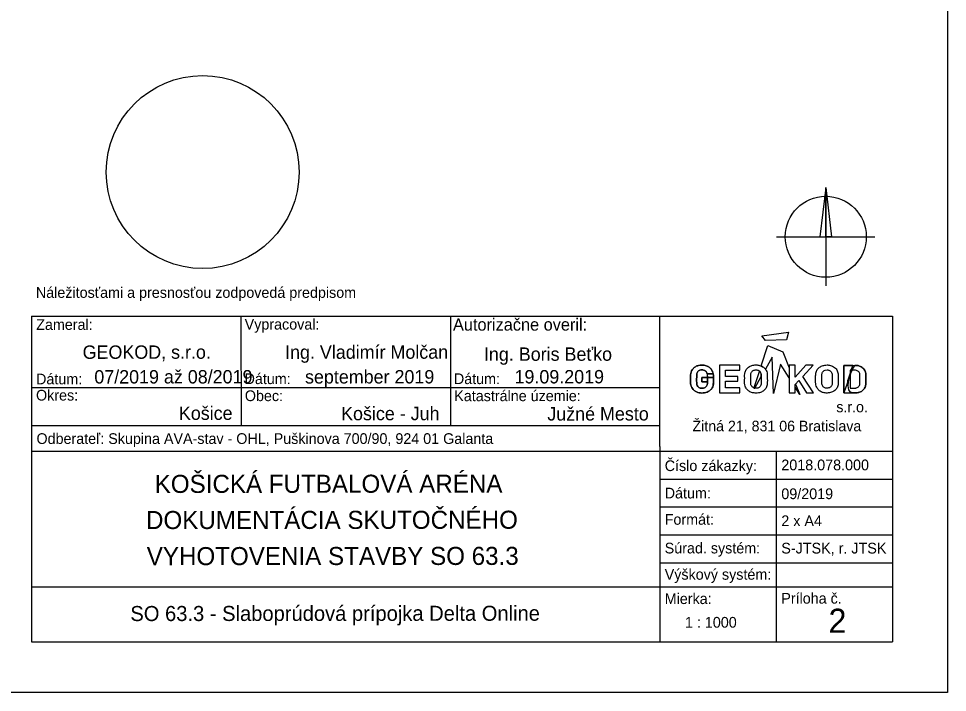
# Model space of a CAD drawing. Extents: x -263995 to -263575, y -1242437 to -1242140.
# Drawn here: x -263776.6 to -263575.4, y -1242437 to -1242291 of the extents above; entities that cross this region are included whole.
import ezdxf

# ---------------------------------------------------------------- set-up
doc = ezdxf.new("R2010")
doc.units = 0
doc.layers.add('RAM_NA_TLAC_A3_1-1000', color=7, linetype='Continuous')
doc.layers.add('ROZPISKA', color=7, linetype='Continuous')

msp = doc.modelspace()

# ---------------------------------------------------------------- linework, layer by layer
at = {"layer": 'RAM_NA_TLAC_A3_1-1000'}
msp.add_lwpolyline([(-263995.41, -1242140.05), (-263575.41, -1242140.05), (-263575.41, -1242437.05), (-263995.41, -1242437.05)], close=True, dxfattribs=at)
at = {"layer": 'ROZPISKA'}
for p, q in [((-263601.78, -1242327.62), (-263603.05, -1242338.28)), ((-263601.78, -1242327.62), (-263601.78, -1242348.94)), ((-263601.78, -1242327.62), (-263600.52, -1242338.28)), ((-263612.44, -1242338.28), (-263591.12, -1242338.28)), ((-263773.82, -1242355.5), (-263587.29, -1242355.5)), ((-263773.82, -1242355.5), (-263773.82, -1242426.09)), ((-263728.46, -1242355.5), (-263728.44, -1242379.21)), ((-263683.08, -1242355.51), (-263683.07, -1242379.2)), ((-263637.7, -1242383.73), (-263637.7, -1242355.5)), ((-263587.29, -1242355.5), (-263587.28, -1242426.09)), ((-263615.78, -1242366.28), (-263614.32, -1242361.85)), ((-263614.32, -1242361.85), (-263611.06, -1242363.23)), ((-263613.38, -1242364.37), (-263614.84, -1242366.98)), ((-263613.1, -1242372.27), (-263613.38, -1242364.37)), ((-263611.06, -1242363.23), (-263609.69, -1242366.72)), ((-263616.97, -1242366.07), (-263616.86, -1242366.06)), ((-263611.54, -1242365.87), (-263613.1, -1242372.27)), ((-263609.69, -1242368.85), (-263611.54, -1242365.87)), ((-263608.42, -1242366.14), (-263609.69, -1242366.14)), ((-263609.69, -1242366.72), (-263609.69, -1242368.85)), ((-263606.11, -1242366.14), (-263608.42, -1242368.75)), ((-263608.42, -1242368.75), (-263608.42, -1242366.14)), ((-263606.72, -1242368.55), (-263604.53, -1242366.14)), ((-263604.53, -1242366.14), (-263606.11, -1242366.14)), ((-263597.82, -1242366.16), (-263595.91, -1242366.16)), ((-263597.82, -1242372.12), (-263597.82, -1242366.16)), ((-263597.82, -1242366.16), (-263597.82, -1242372.12)), ((-263595.91, -1242366.16), (-263597.82, -1242366.16)), ((-263626.11, -1242367.99), (-263627.43, -1242367.99)), ((-263627.43, -1242367.99), (-263626.11, -1242367.99)), ((-263616.14, -1242367.38), (-263617.35, -1242371.06)), ((-263616.94, -1242367.14), (-263616.88, -1242367.13)), ((-263616.94, -1242367.14), (-263616.88, -1242367.13)), ((-263604.41, -1242372.12), (-263606.72, -1242368.55)), ((-263596.51, -1242367.2), (-263596.51, -1242371.08)), ((-263596.51, -1242367.2), (-263596.51, -1242371.08)), ((-263608.31, -1242370.22), (-263607.42, -1242372.5)), ((-263773.83, -1242370.99), (-263637.7, -1242370.99)), ((-263607.42, -1242372.5), (-263608.42, -1242370.89)), ((-263605.91, -1242372.12), (-263604.41, -1242372.12)), ((-263773.82, -1242379.2), (-263637.7, -1242379.2)), ((-263773.84, -1242384.75), (-263637.69, -1242384.74)), ((-263637.7, -1242383.73), (-263637.7, -1242401.89)), ((-263637.69, -1242384.74), (-263587.28, -1242384.74)), ((-263612.49, -1242384.75), (-263612.49, -1242402.9)), ((-263637.7, -1242390.79), (-263587.29, -1242390.8)), ((-263637.71, -1242396.84), (-263587.28, -1242396.84)), ((-263637.71, -1242402.89), (-263587.28, -1242402.9)), ((-263637.7, -1242401.89), (-263637.7, -1242426.08)), ((-263612.49, -1242402.9), (-263612.48, -1242426.08)), ((-263637.7, -1242408.95), (-263587.28, -1242408.94)), ((-263773.83, -1242414.19), (-263587.28, -1242414.18)), ((-263773.82, -1242426.09), (-263587.28, -1242426.09))]:
    msp.add_line(p, q, dxfattribs=at)
for points in [[(-263601.78, -1242327.62), (-263600.52, -1242338.28), (-263601.78, -1242338.28)], [(-263615.61, -1242359.79), (-263609.83, -1242358.96), (-263610.24, -1242360.61), (-263614.84, -1242360.76)], [(-263624.79, -1242366.12), (-263624.79, -1242372.12), (-263620.4, -1242372.12), (-263620.4, -1242371.06), (-263623.47, -1242371.06), (-263623.47, -1242369.62), (-263620.84, -1242369.62), (-263620.84, -1242368.58), (-263623.47, -1242368.58), (-263623.47, -1242367.18), (-263620.4, -1242367.18), (-263620.4, -1242366.12)]]:
    msp.add_lwpolyline(points, close=True, dxfattribs=at)
for points in [[(-263614.84, -1242366.98), (-263614.88, -1242366.93), (-263614.96, -1242366.84), (-263615.04, -1242366.76), (-263615.12, -1242366.69), (-263615.21, -1242366.62), (-263615.31, -1242366.54), (-263615.39, -1242366.49), (-263615.48, -1242366.44), (-263615.59, -1242366.37), (-263615.68, -1242366.32), (-263615.78, -1242366.28)], [(-263609.69, -1242366.14), (-263609.69, -1242372.12), (-263608.42, -1242372.12), (-263608.42, -1242370.33), (-263607.57, -1242369.44), (-263605.91, -1242372.12)], [(-263627.39, -1242369.76), (-263628.64, -1242369.76), (-263628.64, -1242368.77), (-263626.09, -1242368.77)], [(-263626.09, -1242368.77), (-263628.64, -1242368.77), (-263628.64, -1242369.76), (-263627.39, -1242369.76)], [(-263617.15, -1242371.11), (-263615.74, -1242368.6)], [(-263615.74, -1242368.6), (-263615.75, -1242368.46), (-263615.75, -1242368.3), (-263615.76, -1242368.15), (-263615.79, -1242368), (-263615.82, -1242367.87), (-263615.88, -1242367.72), (-263615.96, -1242367.58), (-263616.04, -1242367.47), (-263616.14, -1242367.38)], [(-263608.42, -1242370.89), (-263608.42, -1242370.33), (-263608.31, -1242370.22)], [(-263617.35, -1242371.06), (-263617.32, -1242371.07), (-263617.28, -1242371.08), (-263617.25, -1242371.09), (-263617.21, -1242371.1), (-263617.17, -1242371.11), (-263617.15, -1242371.11)]]:
    msp.add_lwpolyline(points, dxfattribs=at)
for centre, radius in [((-263736.76, -1242324.27), 20.9), ((-263601.78, -1242338.28), 8.78)]:
    msp.add_circle(centre, radius, dxfattribs=at)
for points in [[(-263626.09, -1242368.77), (-263626.09, -1242369.53), (-263626.11, -1242370.21), (-263626.24, -1242370.81), (-263626.53, -1242371.3), (-263626.98, -1242371.71), (-263627.45, -1242371.98), (-263628.07, -1242372.13), (-263628.63, -1242372.17), (-263629.21, -1242372.13), (-263629.8, -1242371.94), (-263630.3, -1242371.61), (-263630.69, -1242371.22), (-263630.94, -1242370.7), (-263631.06, -1242370.11), (-263631.08, -1242369.72), (-263631.08, -1242368.54), (-263631.04, -1242367.9), (-263630.87, -1242367.35), (-263630.57, -1242366.89), (-263629.99, -1242366.42), (-263629.37, -1242366.15), (-263628.65, -1242366.07), (-263627.89, -1242366.13), (-263627.1, -1242366.46), (-263626.47, -1242367.04), (-263626.11, -1242367.99), (-263626.09, -1242368.77), (-263626.11, -1242367.99)], [(-263626.11, -1242367.99), (-263626.47, -1242367.04), (-263627.1, -1242366.46), (-263627.89, -1242366.13), (-263628.65, -1242366.07), (-263629.37, -1242366.15), (-263629.99, -1242366.42), (-263630.57, -1242366.89), (-263630.87, -1242367.35), (-263631.04, -1242367.9), (-263631.08, -1242368.54), (-263631.08, -1242369.72), (-263631.06, -1242370.11), (-263630.94, -1242370.7), (-263630.69, -1242371.22), (-263630.3, -1242371.61), (-263629.8, -1242371.94), (-263629.21, -1242372.13), (-263628.63, -1242372.17), (-263628.07, -1242372.13), (-263627.45, -1242371.98), (-263626.98, -1242371.71), (-263626.53, -1242371.3), (-263626.24, -1242370.81), (-263626.11, -1242370.21), (-263626.09, -1242369.53), (-263626.09, -1242368.77), (-263626.11, -1242367.99), (-263626.09, -1242368.77)], [(-263616.86, -1242366.06), (-263616.83, -1242366.06), (-263616.65, -1242366.06), (-263616.32, -1242366.14), (-263615.87, -1242366.22), (-263615.44, -1242366.45), (-263615.05, -1242366.72), (-263614.74, -1242367.09), (-263614.55, -1242367.51), (-263614.44, -1242367.97), (-263614.44, -1242368.69), (-263614.42, -1242369.44), (-263614.44, -1242370.17), (-263614.5, -1242370.63), (-263614.67, -1242371.02), (-263614.89, -1242371.36), (-263615.2, -1242371.62), (-263615.52, -1242371.86), (-263615.92, -1242372.02), (-263616.36, -1242372.15), (-263616.84, -1242372.18), (-263617.29, -1242372.15), (-263617.68, -1242372.11), (-263618.02, -1242371.96), (-263618.35, -1242371.77), (-263618.66, -1242371.57), (-263618.94, -1242371.28), (-263619.16, -1242370.89), (-263619.32, -1242370.42), (-263619.38, -1242369.64), (-263619.32, -1242368.91), (-263619.36, -1242368.21), (-263619.29, -1242367.81), (-263619.2, -1242367.42), (-263619.01, -1242367.07), (-263618.76, -1242366.79), (-263618.49, -1242366.53), (-263618.15, -1242366.35), (-263617.76, -1242366.18), (-263617.35, -1242366.09), (-263617.08, -1242366.07), (-263616.97, -1242366.07)], [(-263601.48, -1242366.06), (-263601.92, -1242366.1), (-263602.39, -1242366.2), (-263602.78, -1242366.36), (-263603.1, -1242366.55), (-263603.38, -1242366.79), (-263603.61, -1242367.07), (-263603.81, -1242367.43), (-263603.91, -1242367.82), (-263603.96, -1242368.2), (-263603.96, -1242368.62), (-263603.97, -1242369.91), (-263603.92, -1242370.39), (-263603.75, -1242370.92), (-263603.52, -1242371.3), (-263603.29, -1242371.54), (-263602.95, -1242371.78), (-263602.64, -1242371.95), (-263602.32, -1242372.09), (-263601.91, -1242372.15), (-263601.48, -1242372.17), (-263600.97, -1242372.13), (-263600.52, -1242372.01), (-263600.16, -1242371.85), (-263599.81, -1242371.61), (-263599.53, -1242371.35), (-263599.31, -1242371.03), (-263599.14, -1242370.62), (-263599.07, -1242370.2), (-263599.05, -1242369.68), (-263599.06, -1242368.44), (-263599.08, -1242367.96), (-263599.18, -1242367.53), (-263599.39, -1242367.09), (-263599.66, -1242366.76), (-263600.09, -1242366.44), (-263600.48, -1242366.25), (-263600.94, -1242366.14), (-263601.39, -1242366.06), (-263601.48, -1242366.06), (-263601.48, -1242366.06), (-263601.48, -1242366.06)], [(-263595.91, -1242366.16), (-263595.29, -1242366.16), (-263594.9, -1242366.18), (-263594.62, -1242366.24), (-263594.25, -1242366.37), (-263593.9, -1242366.57), (-263593.54, -1242366.9), (-263593.28, -1242367.27), (-263593.15, -1242367.63), (-263593.07, -1242368.18), (-263593.06, -1242368.45), (-263593.06, -1242369.63), (-263593.08, -1242370.02), (-263593.1, -1242370.34), (-263593.16, -1242370.68), (-263593.33, -1242371.09), (-263593.63, -1242371.48), (-263594.07, -1242371.83), (-263594.43, -1242371.99), (-263594.79, -1242372.09), (-263595.1, -1242372.12), (-263595.2, -1242372.12), (-263597.82, -1242372.12), (-263595.91, -1242366.16), (-263597.82, -1242372.12)], [(-263597.82, -1242372.12), (-263595.2, -1242372.12), (-263595.1, -1242372.12), (-263594.79, -1242372.09), (-263594.43, -1242371.99), (-263594.07, -1242371.83), (-263593.63, -1242371.48), (-263593.33, -1242371.09), (-263593.16, -1242370.68), (-263593.1, -1242370.34), (-263593.08, -1242370.02), (-263593.06, -1242369.63), (-263593.06, -1242368.45), (-263593.07, -1242368.18), (-263593.15, -1242367.63), (-263593.28, -1242367.27), (-263593.54, -1242366.9), (-263593.9, -1242366.57), (-263594.25, -1242366.37), (-263594.62, -1242366.24), (-263594.9, -1242366.18), (-263595.29, -1242366.16), (-263595.91, -1242366.16), (-263597.82, -1242372.12), (-263595.91, -1242366.16)], [(-263627.42, -1242367.99), (-263627.55, -1242367.67), (-263627.84, -1242367.35), (-263628.24, -1242367.16), (-263628.63, -1242367.13), (-263629.03, -1242367.18), (-263629.35, -1242367.37), (-263629.59, -1242367.62), (-263629.7, -1242367.89), (-263629.71, -1242368.3), (-263629.74, -1242368.74), (-263629.75, -1242369.28), (-263629.74, -1242369.91), (-263629.69, -1242370.38), (-263629.52, -1242370.75), (-263629.27, -1242370.96), (-263628.97, -1242371.09), (-263628.64, -1242371.13), (-263628.27, -1242371.11), (-263627.87, -1242370.94), (-263627.59, -1242370.67), (-263627.42, -1242370.36), (-263627.38, -1242370), (-263627.39, -1242369.76), (-263627.42, -1242367.99), (-263627.39, -1242369.76)], [(-263627.39, -1242369.76), (-263627.38, -1242370), (-263627.42, -1242370.36), (-263627.59, -1242370.67), (-263627.87, -1242370.94), (-263628.27, -1242371.11), (-263628.64, -1242371.13), (-263628.97, -1242371.09), (-263629.27, -1242370.96), (-263629.52, -1242370.75), (-263629.69, -1242370.38), (-263629.74, -1242369.91), (-263629.75, -1242369.28), (-263629.74, -1242368.74), (-263629.71, -1242368.3), (-263629.7, -1242367.89), (-263629.59, -1242367.62), (-263629.35, -1242367.37), (-263629.03, -1242367.18), (-263628.63, -1242367.13), (-263628.24, -1242367.16), (-263627.84, -1242367.35), (-263627.55, -1242367.67), (-263627.42, -1242367.99), (-263627.39, -1242369.76), (-263627.42, -1242367.99)], [(-263616.88, -1242367.13), (-263616.82, -1242367.13), (-263616.68, -1242367.14), (-263616.44, -1242367.19), (-263616.18, -1242367.33), (-263615.94, -1242367.55), (-263615.8, -1242367.89), (-263615.74, -1242368.26), (-263615.75, -1242368.67), (-263615.73, -1242369.09), (-263615.75, -1242369.53), (-263615.73, -1242369.93), (-263615.79, -1242370.28), (-263615.87, -1242370.58), (-263616.06, -1242370.86), (-263616.34, -1242371.04), (-263616.65, -1242371.13), (-263616.9, -1242371.11), (-263617.12, -1242371.13), (-263617.37, -1242371.07), (-263617.6, -1242370.92), (-263617.83, -1242370.7), (-263617.99, -1242370.38), (-263618.04, -1242369.99), (-263618.02, -1242369.51), (-263618.03, -1242368.99), (-263618.02, -1242368.48), (-263618.01, -1242368.07), (-263617.94, -1242367.74), (-263617.76, -1242367.48), (-263617.52, -1242367.28), (-263617.23, -1242367.15), (-263617.03, -1242367.14), (-263616.94, -1242367.14)], [(-263616.88, -1242367.13), (-263616.82, -1242367.13), (-263616.68, -1242367.14), (-263616.44, -1242367.19), (-263616.18, -1242367.33), (-263615.94, -1242367.55), (-263615.8, -1242367.89), (-263615.74, -1242368.26), (-263615.75, -1242368.67), (-263615.73, -1242369.09), (-263615.75, -1242369.53), (-263615.73, -1242369.93), (-263615.79, -1242370.28), (-263615.87, -1242370.58), (-263616.06, -1242370.86), (-263616.34, -1242371.04), (-263616.65, -1242371.13), (-263616.9, -1242371.11), (-263617.12, -1242371.13), (-263617.37, -1242371.07), (-263617.6, -1242370.92), (-263617.83, -1242370.7), (-263617.99, -1242370.38), (-263618.04, -1242369.99), (-263618.02, -1242369.51), (-263618.03, -1242368.99), (-263618.02, -1242368.48), (-263618.01, -1242368.07), (-263617.94, -1242367.74), (-263617.76, -1242367.48), (-263617.52, -1242367.28), (-263617.23, -1242367.15), (-263617.03, -1242367.14), (-263616.94, -1242367.14)], [(-263601.5, -1242367.13), (-263601.82, -1242367.16), (-263602.13, -1242367.29), (-263602.38, -1242367.5), (-263602.53, -1242367.73), (-263602.62, -1242368.06), (-263602.64, -1242368.42), (-263602.65, -1242368.96), (-263602.65, -1242369.58), (-263602.65, -1242370), (-263602.58, -1242370.38), (-263602.42, -1242370.71), (-263602.21, -1242370.92), (-263601.98, -1242371.05), (-263601.72, -1242371.11), (-263601.52, -1242371.11), (-263601.31, -1242371.11), (-263600.99, -1242371.03), (-263600.67, -1242370.82), (-263600.51, -1242370.58), (-263600.41, -1242370.29), (-263600.36, -1242369.95), (-263600.36, -1242369.56), (-263600.36, -1242369.07), (-263600.36, -1242368.64), (-263600.37, -1242368.29), (-263600.44, -1242367.86), (-263600.58, -1242367.57), (-263600.81, -1242367.34), (-263601.09, -1242367.19), (-263601.33, -1242367.14), (-263601.5, -1242367.13), (-263601.5, -1242367.13), (-263601.5, -1242367.13)], [(-263596.51, -1242371.08), (-263596.13, -1242371.09), (-263595.74, -1242371.09), (-263595.32, -1242371.08), (-263595.25, -1242371.09), (-263595.09, -1242371.05), (-263594.86, -1242370.93), (-263594.55, -1242370.72), (-263594.4, -1242370.35), (-263594.36, -1242369.95), (-263594.37, -1242369.39), (-263594.36, -1242368.75), (-263594.37, -1242368.23), (-263594.4, -1242367.88), (-263594.53, -1242367.64), (-263594.8, -1242367.39), (-263595.1, -1242367.25), (-263595.5, -1242367.19), (-263595.78, -1242367.19), (-263596.34, -1242367.2), (-263596.51, -1242367.2)], [(-263596.51, -1242371.08), (-263596.13, -1242371.09), (-263595.74, -1242371.09), (-263595.32, -1242371.08), (-263595.25, -1242371.09), (-263595.09, -1242371.05), (-263594.86, -1242370.93), (-263594.55, -1242370.72), (-263594.4, -1242370.35), (-263594.36, -1242369.95), (-263594.37, -1242369.39), (-263594.36, -1242368.75), (-263594.37, -1242368.23), (-263594.4, -1242367.88), (-263594.53, -1242367.64), (-263594.8, -1242367.39), (-263595.1, -1242367.25), (-263595.5, -1242367.19), (-263595.78, -1242367.19), (-263596.34, -1242367.2), (-263596.51, -1242367.2)]]:
    msp.add_open_spline(points, degree=3, dxfattribs=at)

# ---------------------------------------------------------------- texts
for s, height, rotation, p in [('Náležitosťami a presnosťou zodpovedá predpisom', 2.3187, 0.0016, (-263772.89, -1242351.53)), ('Zameral:', 2.319, 0.0016, (-263772.82, -1242358.47)), ('Vypracoval:', 2.3187, 0.0016, (-263727.66, -1242358.41)), ('Autorizačne overil:', 2.6427, 0.0016, (-263682.53, -1242358.63)), ('GEOKOD, s.r.o.', 2.8976, 0.0456, (-263762.76, -1242364.75)), ('Ing. Vladimír Molčan', 2.8982, 0.0456, (-263718.9, -1242364.75)), ('Ing. Boris Beťko', 2.8996, 0.0456, (-263675.82, -1242365.18)), ('Dátum:', 2.319, 0.0016, (-263772.85, -1242370.28)), ('07/2019 až 08/2019', 2.8976, 0.0456, (-263760.23, -1242370.1)), ('Dátum:', 2.319, 0.0016, (-263727.68, -1242370.22)), ('september 2019', 2.8976, 0.0456, (-263714.58, -1242370.1)), ('Dátum:', 2.319, 0.0016, (-263682.33, -1242370.22)), ('19.09.2019', 2.898, 0.0456, (-263669.2, -1242370.08)), ('Okres:', 2.319, 0.0016, (-263772.86, -1242373.79)), ('Obec:', 2.319, 0.0016, (-263727.62, -1242373.91)), ('Katastrálne územie:', 2.3187, 0.0016, (-263682.25, -1242373.92)), ('s.r.o.', 2.299, 0.0016, (-263599.48, -1242376.32)), ('Košice', 2.899, 0.0456, (-263741.91, -1242377.98)), ('Košice - Juh', 2.8996, 0.0456, (-263706.77, -1242378.06)), ('Južné Mesto', 2.8996, 0.0456, (-263662.1, -1242378.12)), ('Žitná 21, 831 06 Bratislava', 2.299, 0.0016, (-263630.65, -1242380.46)), ('Odberateľ: Skupina AVA-stav - OHL, Puškinova 700/90, 924 01 Galanta', 2.3181, 0.0016, (-263772.76, -1242383.19)), ('Číslo zákazky:', 2.3181, 0.0016, (-263636.66, -1242389.07)), ('KOŠICKÁ FUTBALOVÁ ARÉNA', 3.9145, 0.0456, (-263747.15, -1242393.81)), ('Dátum:', 2.319, 0.0016, (-263636.66, -1242395)), ('DOKUMENTÁCIA SKUTOČNÉHO', 3.9145, 0.0456, (-263749.03, -1242401.64)), ('Formát:', 2.319, 0.0016, (-263636.66, -1242400.7)), ('Súrad. systém:', 2.3181, 0.0016, (-263636.66, -1242406.92)), ('VYHOTOVENIA STAVBY SO 63.3', 3.9145, 0.0456, (-263748.87, -1242409.47)), ('Výškový systém:', 2.3181, 0.0016, (-263636.66, -1242412.62)), ('Mierka:', 2.319, 0.0016, (-263636.66, -1242417.89)), ('Príloha č.', 2.318, 0.0016, (-263611.4, -1242417.81)), ('SO 63.3 - Slaboprúdová prípojka Delta Online', 3.2613, 0.0456, (-263752.42, -1242421.58))]:
    msp.add_text(s, height=height, rotation=rotation, dxfattribs=at).set_placement(p)
for s, height, p in [('2018.078.000', 2.322, (-263611.4, -1242388.9)), ('09/2019', 2.322, (-263611.4, -1242395.15)), ('2 x A4', 2.322, (-263611.4, -1242401.01)), ('S-JTSK, r. JTSK', 2.322, (-263611.4, -1242406.94)), ('2', 5.22, (-263601.17, -1242424.12)), ('1 : 1000', 2.322, (-263632.28, -1242423.01))]:
    msp.add_text(s, height=height, dxfattribs=at).set_placement(p)

doc.saveas('drawing.dxf')
